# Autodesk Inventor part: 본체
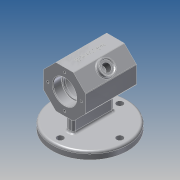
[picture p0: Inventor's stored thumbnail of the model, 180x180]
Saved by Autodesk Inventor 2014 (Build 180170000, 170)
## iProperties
Created: 2021-02
Part Number: 본체
Material: 알루미늄 6061
Document SubType Name: Modeling
Designer: kb542
Density: 2.71 g/cm^3
Appearance: 알루미늄 - 평지
Mass: 558.806 g
Surface Area: 509.67 cm^2
Volume: 206.202 cm^3
Author: kb542
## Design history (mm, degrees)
sketch "스케치1" dims "d0" = 58
  geometry: L1 (-12.012, -29)-(-29, -12.012); L2 (-29, -12.012)-(-29, 12.012); L3 (-29, 12.012)-(-12.012, 29); L4 (-12.012, 29)-(12.012, 29); L5 (12.012, 29)-(29, 12.012); L6 (29, 12.012)-(29, -12.012); L7 (29, -12.012)-(12.012, -29); L8 (12.012, -29)-(-12.012, -29); 4 further points
  constraints: 16 end point, 2 coincident, 1 midpoint, 1 vertical, 1 vertical alignment, 19 other
extrude "돌출1" new body sketch "스케치1" distance "d1" = 70; taper "d2" = 0 deg
sketch "스케치2"
  geometry: L1 (0, 29)-(0, 12.012) reference; L2 (0, 12.012)-(0, -12.012) reference; L3 (0, 29)-(70, 29) reference; L4 (70, 12.012)-(70, 29) reference; L5 (70, -12.012)-(70, 12.012) reference; L6 (0, 16)-(12, 16); L7 (12, 16)-(12, 14); L8 (12, 14)-(15, 14); L9 (15, 14)-(15, 22); L10 (15, 22)-(55, 22); L11 (55, 22)-(55, 14); L12 (55, 14)-(58, 14); L13 (58, 14)-(58, 16); L14 (58, 16)-(70, 16); L15 (0, 0)-(70, 0); L16 (0, 16)-(0, 0); L17 (70, 16)-(70, 0)
  constraints: 24 end point, 6 parallel, 5 collinear, 4 perpendicular, 2 point on line, 1 midpoint
  dimensions: "d3" = 28 diameter of L8 L15; "d4" = 32 diameter of L6 L15; "d5" = 12 distance from line of L7 L1.end; "d6" = 3 distance between parallel lines of L9 L7; "d7" = 44 diameter of L10 L15
revolve "회전1" sketch "스케치2" stored, may be unused: angle "d8" = 90 deg
sketch "스케치3" dims "d9" = 46
  geometry: C1 r 16 at (0, 0) reference; 5 further points
  constraints: 2 vertical alignment, 1 coincident, 7 other
  dimensions: "d12" = 360 deg dimension on C1.centre point (0, 23) (derived)
hole "구멍1" sketch "스케치3" at (0, 23), (-23, 0), (0, -23), (23, 0) diameter "d14" = 3.242; stored, may be unused: countersink angle "d18" = 90 deg, drill point angle "d20" = 118 deg; dims "d15" = 8, "d16" = 4, "d17" = 2, "d19" = 10
node "작업 평면1"
sketch "스케치4"
  geometry: L1 (0, 0)-(24.042, 24.042); L2 (0, 0)-(0, 29); L3 (-12.012, 29)-(12.012, 29) reference
  constraints: 4 end point, 1 midpoint
  dimensions: "d21" = 34 distance of L1.end L1.start; "d22" = 45 deg angle of L2 L1
node "작업 평면2"
sketch "스케치5"
  geometry: L1 (-35, 29)-(35, 29) reference; L2 (-35, -12.012)-(-35, 12.012) reference; C1 r 10 at (0, 0); 1 further point
  constraints: 1 centre point
  dimensions: "d23" = 20 diameter of C1; "d24" = 29 distance from line of C1.centre L1; "d25" = 35 distance from line of C1.centre L2
extrude "돌출2" join sketch "스케치5" stored distance "d26" = 70; taper "d27" = 0 deg
hole "구멍2" diameter "d30" = 10.917; stored, may be unused: countersink angle "d34" = 90 deg, drill point angle "d36" = 118 deg; dims "d28" = 10, "d29" = 10, "d31" = 15, "d32" = 16, "d33" = 2, "d35" = 15
node "작업 평면3"
sketch "스케치6" dims "d39" = 82
  geometry: L1 (-29, 0)-(-29, 70) reference; C1 r 52 at (0, 35); C2 r 4.5 at (-41, 35); C3 r 4.5 at (0, -6); C4 r 4.5 at (41, 35); C5 r 4.5 at (0, 76); 3 further points
  constraints: 5 centre point, 2 horizontal alignment, 2 vertical alignment, 1 coincident, 1 midpoint, 11 other
  dimensions: "d38" = 104 diameter of C1; "d42" = 360 deg dimension on C1.centre C2.centre (derived); "d44" = 9 diameter of C2
extrude "돌출3" join sketch "스케치6" distance "d45" = 10; taper "d46" = 0 deg
sketch "스케치7"
  geometry: L1 (-5, -28)-(5, -28); L2 (5, -28)-(5, 28); L3 (5, 28)-(-5, 28); L4 (-5, 28)-(-5, -28); C1 r 4.5 at (-41, 0) reference; 3 further points
  constraints: 8 end point, 2 midpoint, 2 parallel, 1 horizontal, 1 horizontal alignment, 1 perpendicular, 1 vertical alignment
  dimensions: "d47" = 10 distance between parallel lines of L2 L4; "d48" = 56 distance between parallel lines of L3 L1
extrude "돌출4" join sketch "스케치7" stored distance "d49" = 10; taper "d50" = 0 deg
fillet "모깎기1" dims "d51" = 3, "d54" = 1
fillet "모깎기3" dims "d55" = 3, "d56" = 0.3
chamfer "모따기1" distance "d57" = 1; stored, may be unused: second distance "d58" = 2, angle "d59" = 45 deg
node "작업 평면4"
sketch "스케치8"
  geometry: L1 (-17.402, 70)-(-17.402, 0) reference; 2 further points
  constraints: 1 other
  dimensions: "d61" = 35 distance of point (11.598, 35) point (11.598, 0); "d62" = 29 distance from line of point (11.598, 35) L1
feature "엠보싱1" sketch "스케치8" dims "d0" = 58, "d63" = 0.5, "d64" = 0
node "솔리드1"
mirror "대칭1"
other parameters: "d37" = -62, "d60" = 21.5
